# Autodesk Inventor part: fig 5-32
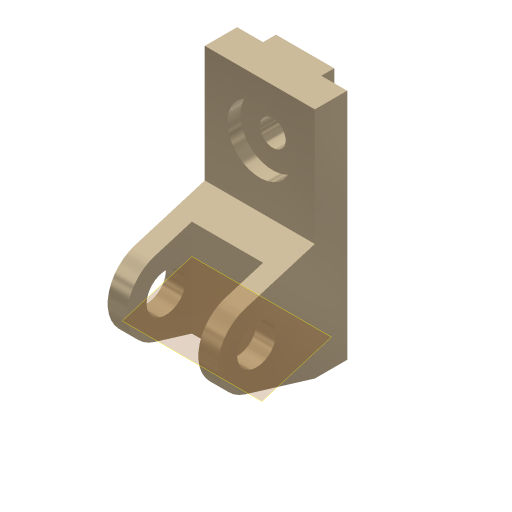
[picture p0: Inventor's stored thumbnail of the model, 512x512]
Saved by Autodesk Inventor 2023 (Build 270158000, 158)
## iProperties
Created: 2001-11
Part Number: fig 5-32
Document SubType Name: Modeling
Designer: Renu Muthoo
Density: 1 g/cm^3
Material: Generic
Appearance: Metal-Titanium (Polished)
Control State: 0
Master: False
Checked Out: False
Shininess: 65.0
Angle Display Precision: 2
Document Length Units: 11269
Document Angle Units: 11279
Document Time Units: 11290
Document Mass Units: 11283
Document Length Units Precision: 3
Document Angle Units Precision: 2
Density: 0.0
Volumn: 0.0
Area: 0.0
PropertySet Name: Model Information
Author: Renu Muthoo
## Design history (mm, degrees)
node "Sketch1"
sketch "Sketch2"
  geometry: L1 (33.257, 104.664)-(33.257, -75.336); L2 (33.257, -75.336)-(8.257, -75.336); L3 (8.257, -75.336)-(-45.451, -59.045); L4 (-45.451, -1.628)-(8.257, 14.664); L5 (8.257, 14.664)-(8.257, 104.664); L6 (8.257, 104.664)-(33.257, 104.664); C1 r 15 at (-36.743, -30.336); A1 r 30 centre (-36.743, -30.336) between (-45.451, -1.628) and (-45.451, -59.045)
  constraints: 12 end point, 2 centre point, 2 equal length, 2 parallel, 2 point on circle, 2 tangent, 1 coincident, 1 perpendicular, 1 vertical
  dimensions: "d0" = 180 distance of L1.start L1.end; "d1" = 30 radius of A1; "d2" = 25 distance of L5.end L1.start; "d3" = 45 distance from line of L2 A1.centre; "d4" = 70 distance from line of L1 A1.centre; "d5" = 30 diameter of C1
extrude "Extrusion1" new body sketch "Sketch2" distance "d6" = 85; taper "d7" = 0 deg
workplane "Work Plane1"
sketch "Sketch3"
  geometry: L1 (15, 62.364)-(70, 62.364); L2 (70, 62.364)-(70, -52.386); L3 (70, -52.386)-(15, -52.386); L4 (15, -52.386)-(15, 62.364); L5 (0, -45)-(0, -28.708) reference
  constraints: 8 end point, 2 parallel, 1 horizontal, 1 perpendicular
  dimensions: "d8" = 55 distance of L1.start L1.end; "d9" = 15 distance between parallel lines of L5 L4
extrude "Extrusion2" cut sketch "Sketch3" distance "d10" = 50; taper "d11" = 0 deg
sketch "Sketch4"
  geometry: L1 (0, 25)-(85, 25) reference; L2 (0, 0)-(0, 25) reference; L3 (20, 25)-(65, 25); L4 (65, 25)-(65, 35); L5 (65, 35)-(20, 35); L6 (20, 35)-(20, 25)
  constraints: 8 end point, 2 parallel, 1 horizontal, 1 perpendicular, 1 point on line
  dimensions: "d12" = 45 distance of L4.end L5.end; "d13" = 10 distance of L3.end L4.end; "d14" = 20 distance between parallel lines of L2 L6
extrude "Extrusion3" join sketch "Sketch4" stored distance "d15" = 50; taper "d16" = 0 deg
sketch "Sketch5"
  geometry: L1 (85, 0)-(85, 90) reference; L2 (0, 90)-(85, 90) reference; 1 further point
  dimensions: "d17" = 42 distance from line of L2 point (42.5, 48); "d18" = 42.5 distance from line of L1 point (42.5, 48)
hole "Hole1" sketch "Sketch5" at (42.5, 48) diameter "d19" = 20; stored, may be unused: countersink angle "d23" = 82 deg, drill point angle "d25" = 118 deg; dims "d20" = 6, "d21" = 50, "d22" = 10, "d24" = 8
workplane "Work Plane6"
body "Solid1"
